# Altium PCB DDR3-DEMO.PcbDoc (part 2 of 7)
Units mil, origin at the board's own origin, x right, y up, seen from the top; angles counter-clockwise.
Board outline 2827 x 2165.35 mil, 8 copper layers (TOP, GND02, ART03, ART04, PWR05, ART06, GND07, BOTTOM); 111 components, 133 nets, 5542 pads, 873 vias.
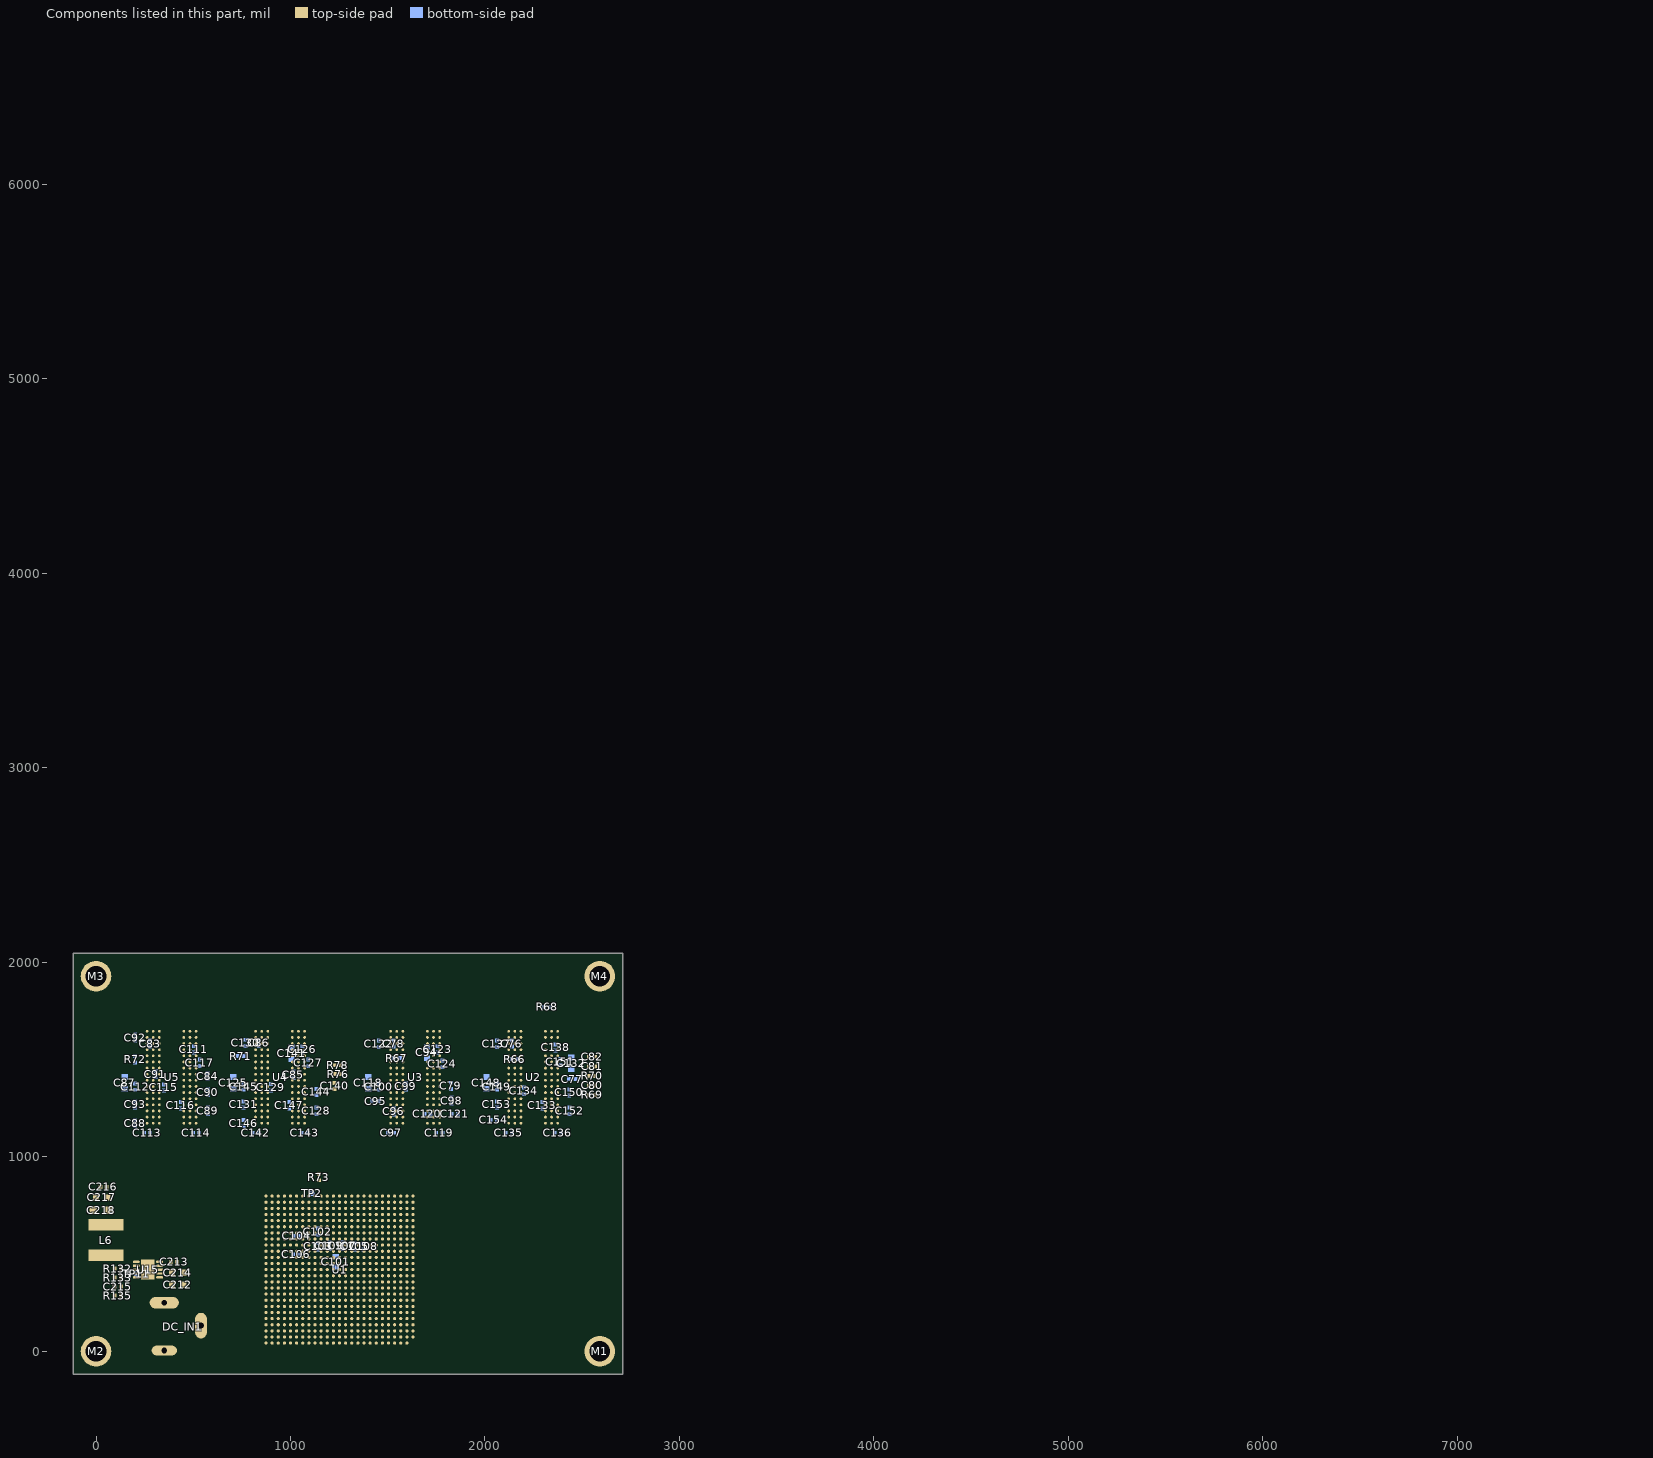
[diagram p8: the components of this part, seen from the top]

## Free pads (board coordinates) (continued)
  round 6 on Drill Drawing: 1(4045.04,1424.5) 1(4045.04,1424.5) 1(4045.04,1459.5) 1(4065.04,1424.5) 1(4072.54,1424.5) 1(4077.04,1436.75) 1(4085.04,1459.5) 1(4085.04,1459.5) 1(4093.04,1436.75) 1(4097.54,1424.5) 1(4105.04,1459.5) 1(4115.04,1424.5) 1(4115.04,1440.25) 1(4115.04,1440.25) 1(4115.04,1440.25) 1(4125.04,1459.5) 1(4129.07,554.03) 1(4129.07,554.03) 1(4129.07,589.03) 1(4135.04,1424.5) 1(4135.04,1424.5) 1(4135.04,1442.58) 1(4135.04,1459.5) 1(4135.04,1459.5) 1(4147.04,1442.58) 1(4149.07,554.03) 1(4155.04,1424.5) 1(4155.04,1459.5) 1(4156.04,2146.59) 1(4156.04,2366.59) 1(4156.04,2586.59) 1(4156.04,2806.59) 1(4156.04,3026.59) 1(4156.04,3246.59) 1(4156.04,3466.59) 1(4156.57,554.03) 1(4161.07,566.28) 1(4165.04,1424.5) 1(4165.04,1441.42) 1(4165.04,1459.5) 1(4165.04,1459.5) 1(4169.07,589.03) 1(4169.07,589.03) 1(4177.07,566.28) 1(4177.54,1441.42) 1(4177.54,1441.42) 1(4177.54,1441.42) 1(4177.54,1459.5) 1(4177.54,1459.5) 1(4181.04,1443.17) 1(4181.04,1443.17) 1(4181.54,1457.75) 1(4181.54,1457.75) 1(4181.57,554.03) 1(4184.04,1446.08) 1(4184.04,1446.08) 1(4184.04,1455.42) 1(4184.04,1455.42) 1(4185.04,1424.5) 1(4185.04,1450.75) 1(4185.04,1450.75) 1(4189.07,589.03) 1(4199.07,554.03) 1(4199.07,569.78) 1(4199.07,569.78) 1(4199.07,569.78) 1(4209.07,589.03) 1(4219.07,554.03) 1(4219.07,554.03) 1(4219.07,572.11) 1(4219.07,589.03) 1(4219.07,589.03) 1(4231.07,572.11) 1(4236.04,2126.59) 1(4236.04,2126.59) 1(4236.04,2166.59) 1(4236.04,2166.59) 1(4236.04,2346.59) 1(4236.04,2346.59) 1(4236.04,2386.59) 1(4236.04,2386.59) 1(4236.04,2566.59) 1(4236.04,2566.59) 1(4236.04,2606.59) 1(4236.04,2606.59) 1(4236.04,2786.59) 1(4236.04,2786.59) 1(4236.04,2826.59) 1(4236.04,2826.59) 1(4236.04,3006.59) 1(4236.04,3006.59) 1(4236.04,3046.59) 1(4236.04,3046.59) 1(4236.04,3226.59) 1(4236.04,3226.59) 1(4236.04,3266.59) 1(4236.04,3266.59) 1(4236.04,3446.59) 1(4236.04,3446.59) 1(4236.04,3486.59) 1(4236.04,3486.59) 1(4239.07,554.03) 1(4239.07,589.03) 1(4249.07,554.03) 1(4249.07,570.95) 1(4249.07,589.03) 1(4249.07,589.03) 1(4261.57,570.95) 1(4261.57,570.95) 1(4261.57,570.95) 1(4261.57,589.03) 1(4261.57,589.03) 1(4265.07,572.7) 1(4265.07,572.7) 1(4265.57,587.28) 1(4265.57,587.28) 1(4268.07,575.61) 1(4268.07,575.61) 1(4268.07,584.95) 1(4268.07,584.95) 1(4269.07,554.03) 1(4269.07,580.28) 1(4269.07,580.28) 1(4291.04,2146.59) 1(4291.04,2146.59) 1(4291.04,2146.59) 1(4291.04,2366.59) 1(4291.04,2366.59) 1(4291.04,2366.59) 1(4291.04,2586.59) 1(4291.04,2586.59) 1(4291.04,2586.59) 1(4291.04,2806.59) 1(4291.04,2806.59) 1(4291.04,2806.59) 1(4291.04,3026.59) 1(4291.04,3026.59) 1(4291.04,3026.59) 1(4291.04,3246.59) 1(4291.04,3246.59) 1(4291.04,3246.59) 1(4291.04,3466.59) 1(4291.04,3466.59) 1(4291.04,3466.59) 1(4386.54,2112.42) 1(4386.54,2162.42) 1(4386.54,2332.11) 1(4386.54,2382.11) 1(4386.54,2551.79) 1(4386.54,2601.79) 1(4386.54,2771.48) 1(4386.54,2821.48) 1(4386.54,2991.16) 1(4386.54,3041.16) 1(4386.54,3210.85) 1(4386.54,3260.85) 1(4386.54,3430.53) 1(4386.54,3480.53) 1(4421.54,2097.42) 1(4421.54,2317.11) 1(4421.54,2536.79) 1(4421.54,2756.48) 1(4421.54,2976.16) 1(4421.54,3195.85) 1(4421.54,3415.53) 1(4426.54,2202.42) 1(4426.54,2422.11) 1(4426.54,2641.79) 1(4426.54,2861.48) 1(4426.54,3081.16) 1(4426.54,3300.85) 1(4426.54,3520.53) 1(4471.54,2097.42) 1(4471.54,2317.11) 1(4471.54,2536.79) 1(4471.54,2756.48) 1(4471.54,2976.16) 1(4471.54,3195.85) 1(4471.54,3415.53) 1(4476.54,2202.42) 1(4476.54,2422.11) 1(4476.54,2641.79) 1(4476.54,2861.48) 1(4476.54,3081.16) 1(4476.54,3300.85) 1(4476.54,3520.53) 1(4519.59,1458.47) 1(4521.54,2097.42) 1(4521.54,2317.11) 1(4521.54,2536.79) 1(4521.54,2756.48) 1(4521.54,2976.16) 1(4521.54,3195.85) 1(4521.54,3415.53) 1(4526.54,2202.42) 1(4526.54,2422.11) 1(4526.54,2641.79) 1(4526.54,2861.48) 1(4526.54,3081.16) 1(4526.54,3300.85) 1(4526.54,3520.53) 1(4526.59,1423.47) 1(4526.59,1423.47) 1(4534.59,1458.47) 1(4534.59,1458.47) 1(4542.59,1423.47) 1(4542.59,1423.47) 1(4549.59,1458.47) 1(4553.6,597.7) 1(4558.59,1423.47) 1(4558.59,1458.47) 1(4560.6,562.7) 1(4560.6,562.7) 1(4564.59,1423.47) 1(4564.59,1458.47) 1(4568.6,597.7) 1(4568.6,597.7) 1(4570.59,1423.47) 1(4570.59,1458.47) 1(4576.54,2202.42) 1(4576.54,2422.11) 1(4576.54,2641.79) 1(4576.54,2861.48) 1(4576.54,3081.16) 1(4576.54,3300.85) 1(4576.54,3520.53) 1(4576.6,562.7) 1(4576.6,562.7) 1(4583.59,1423.47) 1(4583.59,1423.47) 1(4583.59,1458.47) 1(4583.59,1458.47) 1(4583.6,597.7) 1(4592.6,562.7) 1(4592.6,597.7) 1(4593.59,1423.47) 1(4593.59,1423.47) 1(4593.59,1458.47) 1(4593.59,1458.47) 1(4597.59,1425.22) 1(4597.59,1425.22) 1(4597.59,1456.72) 1(4597.59,1456.72) 1(4598.6,562.7) 1(4598.6,597.7) 1(4600.59,1427.55) 1(4600.59,1427.55) 1(4600.59,1454.39) 1(4600.59,1454.39) 1(4603.09,1431.05) 1(4603.09,1431.05) 1(4603.09,1450.89) 1(4603.09,1450.89) 1(4604.6,562.7) 1(4604.6,597.7) 1(4605.09,1435.14) 1(4605.09,1435.14) 1(4605.09,1446.8) 1(4605.09,1446.8) 1(4605.59,1440.97) 1(4605.59,1440.97) 1(4613.09,1458.47) 1(4617.6,562.7) 1(4617.6,562.7) 1(4617.6,597.7) 1(4617.6,597.7) 1(4624.59,1423.47) 1(4624.59,1458.47) 1(4626.54,2202.42) 1(4626.54,2422.11) 1(4626.54,2641.79) 1(4626.54,2861.48) 1(4626.54,3081.16) 1(4626.54,3300.85) 1(4626.54,3520.53) 1(4627.6,562.7) 1(4627.6,562.7) 1(4627.6,597.7) 1(4627.6,597.7) 1(4631.6,564.45) 1(4631.6,564.45) 1(4631.6,595.95) 1(4631.6,595.95) 1(4634.6,566.78) 1(4634.6,566.78) 1(4634.6,593.62) 1(4634.6,593.62) 1(4636.09,1458.47) 1(4637.1,570.28) 1(4637.1,570.28) 1(4637.1,590.12) 1(4637.1,590.12) 1(4639.1,574.37) 1(4639.1,574.37) 1(4639.1,586.03) 1(4639.1,586.03) 1(4639.6,580.2) 1(4639.6,580.2) 1(4644.09,1423.47) 1(4644.09,1440.97) 1(4644.09,1458.47) 1(4647.1,597.7) 1(4658.6,562.7) 1(4658.6,597.7) 1(4665.09,1423.47) 1(4665.09,1440.97) 1(4665.09,1458.47) 1(4670.1,597.7) 1(4678.1,562.7) 1(4678.1,580.2) 1(4678.1,597.7) 1(4699.1,562.7) 1(4699.1,580.2) 1(4699.1,597.7) 1(4751.9,1431.64) 1(4751.9,1431.64) 1(4751.9,1454.97) 1(4751.9,1454.97) 1(4754.4,1425.81) 1(4754.4,1425.81) 1(4754.4,1460.81) 1(4754.4,1460.81) 1(4758.6,562.7) 1(4758.6,562.7) 1(4758.6,586.03) 1(4758.6,586.03) 1(4759.4,1419.97) 1(4759.4,1466.64) 1(4761.1,556.87) 1(4761.1,556.87) 1(4761.1,591.87) 1(4761.1,591.87) 1(4766.1,551.03) 1(4766.1,597.7) 1(4776.9,1431.64) 1(4776.9,1448.56) 1(4776.9,1454.97) 1(4778.4,1451.47) 1(4778.4,1451.47) 1(4780.9,1453.81) 1(4780.9,1453.81) 1(4783.6,562.7) 1(4783.6,579.62) 1(4783.6,586.03) 1(4784.4,1454.97) 1(4784.4,1454.97) 1(4785.1,582.53) 1(4785.1,582.53) 1(4787.6,584.87) 1(4787.6,584.87) 1(4787.9,1453.81) 1(4787.9,1453.81) 1(4790.4,1451.47) 1(4790.4,1451.47) 1(4791.1,586.03) 1(4791.1,586.03) 1(4791.9,1431.64) 1(4791.9,1448.56) 1(4791.9,1448.56) 1(4791.9,1448.56) 1(4793.4,1451.47) 1(4793.4,1451.47) 1(4794.6,584.87) 1(4794.6,584.87) 1(4795.9,1453.81) 1(4795.9,1453.81) 1(4797.1,582.53) 1(4797.1,582.53) 1(4798.6,562.7) 1(4798.6,579.62) 1(4798.6,579.62) 1(4798.6,579.62) 1(4799.4,1454.97) 1(4799.4,1454.97) 1(4800.1,582.53) 1(4800.1,582.53) 1(4802.6,584.87) 1(4802.6,584.87) 1(4802.9,1453.81) 1(4802.9,1453.81) 1(4805.4,1451.47) 1(4805.4,1451.47) 1(4806.1,586.03) 1(4806.1,586.03) 1(4806.9,1431.64) 1(4806.9,1447.97) 1(4806.9,1447.97) 1(4809.6,584.87) 1(4809.6,584.87) 1(4812.1,582.53) 1(4812.1,582.53) 1(4813.6,562.7) 1(4813.6,579.03) 1(4813.6,579.03) 1(4820.9,1464.89) 1(4820.9,1464.89) 1(4820.9,1466.06) 1(4820.9,1466.06) 1(4821.9,1431.64) 1(4821.9,1454.97) 1(4821.9,1464.31) 1(4821.9,1464.31) 1(4821.9,1466.64) 1(4821.9,1466.64) 1(4822.9,1464.89) 1(4822.9,1464.89) 1(4822.9,1466.06) 1(4822.9,1466.06) 1(4827.6,595.95) 1(4827.6,595.95) 1(4827.6,597.12) 1(4827.6,597.12) 1(4828.6,562.7) 1(4828.6,586.03) 1(4828.6,595.37) 1(4828.6,595.37) 1(4828.6,597.7) 1(4828.6,597.7) 1(4829.6,595.95) 1(4829.6,595.95) 1(4829.6,597.12) 1(4829.6,597.12) 1(4851.9,1431.64) 1(4851.9,1466.64) 1(4858.6,562.7) 1(4858.6,597.7) 1(4884.4,1419.97) 1(4884.4,1466.64) 1(4889.4,1425.81) 1(4889.4,1425.81) 1(4889.4,1460.81) 1(4889.4,1460.81) 1(4891.1,551.03) 1(4891.1,597.7) 1(4891.9,1431.64) 1(4891.9,1431.64) 1(4891.9,1454.97) 1(4891.9,1454.97) 1(4896.1,556.87) 1(4896.1,556.87) 1(4896.1,591.87) 1(4896.1,591.87) 1(4898.6,562.7) 1(4898.6,562.7) 1(4898.6,586.03) 1(4898.6,586.03) 1(4924.73,3869.47) 1(4924.73,3869.47) 1(4924.73,3932.47) 1(4928.9,3852.47) 1(4956.07,3869.47) 1(4983.82,3869.47) 1(4990.87,3891.52) 1(5003.4,3932.47) 1(5003.4,3932.47) 1(5015.93,3891.52) 1(5022.98,3869.47) 1(5048.63,1878.63) 1(5048.63,1878.63) 1(5048.63,1912.23) 1(5048.63,1941.63) 1(5048.63,1941.63) 1(5050.73,3932.47) 1(5066.4,3869.47) 1(5066.4,3897.82) 1(5066.4,3897.82) 1(5066.4,3897.82) 1(5069.78,1941.63) 1(5069.78,1941.63) 1(5072.92,1912.23) 1(5072.92,1912.23) 1(5072.92,1912.23) 1(5074.48,1878.63) 1(5074.48,1878.63) 1(5075.27,1938.48) 1(5075.27,1938.48) 1(5076.05,1915.38) 1(5076.05,1915.38) 1(5078.4,1910.13) 1(5078.4,1910.13) 1(5078.4,1920.63) 1(5078.4,1920.63) 1(5078.4,1934.28) 1(5078.4,1934.28) 1(5079.97,1882.83) 1(5079.97,1882.83) 1(5079.97,1927.98) 1(5079.97,1927.98) 1(5082.07,3932.47) 1(5083.1,1889.13) 1(5083.1,1889.13) 1(5083.1,1903.83) 1(5083.1,1903.83) 1(5084.67,1896.48) 1(5084.67,1896.48) 1(5097.33,1428.85) 1(5097.33,1463.85) 1(5103.33,1428.85) 1(5103.33,1463.85) 1(5108.5,1905.93) 1(5108.5,1905.93) 1(5108.5,1914.33) 1(5108.5,1914.33) 1(5109.33,1428.85) 1(5109.33,1463.85) 1(5110.07,1897.53) 1(5110.07,1897.53) 1(5110.07,1922.73) 1(5110.07,1922.73) 1(5113.2,1890.18) 1(5113.2,1890.18) 1(5113.2,1930.08) 1(5113.2,1930.08) 1(5113.73,3869.47) 1(5113.73,3869.47) 1(5113.73,3902.02) 1(5113.73,3932.47) 1(5113.73,3932.47) 1(5117.9,1883.88) 1(5117.9,1883.88) 1(5117.9,1936.38) 1(5117.9,1936.38) 1(5120.09,3755.47) 1(5120.33,1428.85) 1(5120.33,1463.85) 1(5120.33,1463.85) 1(5123.38,1879.68) 1(5123.38,1879.68) 1(5123.38,1940.58) 1(5123.38,1940.58) 1(5129.65,1878.63) 1(5129.65,1878.63) 1(5129.65,1941.63) 1(5129.65,1941.63) 1(5132.53,3902.02) 1(5133.33,1434.68) 1(5133.33,1434.68) 1(5135.92,1879.68) 1(5135.92,1879.68) 1(5135.92,1940.58) 1(5135.92,1940.58) 1(5138.11,3692.47) 1(5138.11,3755.47) 1(5141.4,1883.88) 1(5141.4,1883.88) 1(5141.4,1936.38) 1(5141.4,1936.38) 1(5145.07,3869.47) 1(5145.07,3932.47) 1(5146.1,1890.18) 1(5146.1,1890.18) 1(5146.1,1930.08) 1(5146.1,1930.08) 1(5146.33,1428.85) 1(5146.33,1463.85) 1(5146.33,1463.85) 1(5146.85,553.64) 1(5146.85,588.64) 1(5149.23,1897.53) 1(5149.23,1897.53) 1(5149.23,1922.73) 1(5149.23,1922.73) 1(5150.8,1905.93) 1(5150.8,1905.93) 1(5150.8,1914.33) 1(5150.8,1914.33) 1(5152.85,553.64) 1(5152.85,588.64) 1(5153.33,1428.85) 1(5153.33,1443.43) 1(5153.33,1463.85) 1(5153.33,1463.85) 1(5156.13,3755.47) 1(5158.85,553.64) 1(5158.85,588.64) 1(5165.33,1443.43) 1(5165.33,1443.43) 1(5165.33,1463.85) 1(5165.33,1463.85) 1(5169.33,1462.1) 1(5169.33,1462.1) 1(5169.83,1445.18) 1(5169.83,1445.18) 1(5169.85,553.64) 1(5169.85,588.64) 1(5169.85,588.64) 1(5172.33,1448.68) 1(5172.33,1448.68) 1(5172.33,1458.02) 1(5172.33,1458.02) 1(5173.33,1453.35) 1(5173.33,1453.35) 1(5174.63,1941.63) 1(5176.73,3869.47) 1(5176.73,3899.92) 1(5176.73,3932.47) 1(5176.73,3932.47) 1(5179.96,3719.77) 1(5179.96,3719.77) 1(5179.96,3728.17) 1(5179.96,3728.17) 1(5181.53,3711.37) 1(5181.53,3711.37) 1(5181.53,3736.57) 1(5181.53,3736.57) 1(5182.85,559.47) 1(5182.85,559.47) 1(5183.33,1428.85) 1(5183.33,1428.85) 1(5183.33,1446.93) 1(5183.33,1463.85) 1(5183.33,1463.85) 1(5184.66,3704.02) 1(5184.66,3704.02) 1(5184.66,3743.92) 1(5184.66,3743.92) 1(5189.36,3697.72) 1(5189.36,3697.72) 1(5189.36,3750.22) 1(5189.36,3750.22) 1(5192.65,1878.63) 1(5192.65,1941.63) 1(5194.84,3693.52) 1(5194.84,3693.52) 1(5194.84,3754.42) 1(5194.84,3754.42) 1(5195.33,1446.93) 1(5195.85,553.64) 1(5195.85,588.64) 1(5195.85,588.64) 1(5196.32,3899.92) 1(5196.32,3899.92) 1(5196.32,3899.92) 1(5196.32,3932.47) 1(5196.32,3932.47) 1(5201.11,3692.47) 1(5201.11,3692.47) 1(5201.11,3755.47) 1(5201.11,3755.47) 1(5201.8,3903.07) 1(5201.8,3903.07) 1(5202.58,3929.32) 1(5202.58,3929.32) 1(5202.85,553.64) 1(5202.85,568.22) 1(5202.85,588.64) 1(5202.85,588.64) 1(5203.33,1428.85) 1(5203.33,1463.85) 1(5206.5,3908.32) 1(5206.5,3908.32) 1(5206.5,3925.12) 1(5206.5,3925.12) 1(5207.38,3693.52) 1(5207.38,3693.52) 1(5207.38,3754.42) 1(5207.38,3754.42) 1(5208.07,3869.47) 1(5208.07,3916.72) 1(5208.07,3916.72) 1(5210.67,1941.63) 1(5212.33,1428.85) 1(5212.33,1428.85) 1(5212.33,1463.85) 1(5212.33,1463.85) 1(5212.86,3697.72) 1(5212.86,3697.72) 1(5212.86,3750.22) 1(5212.86,3750.22) 1(5214.85,568.22) 1(5214.85,568.22) 1(5214.85,588.64) 1(5214.85,588.64) 1(5217.56,3704.02) 1(5217.56,3704.02) 1(5217.56,3743.92) 1(5217.56,3743.92) 1(5218.85,586.89) 1(5218.85,586.89) 1(5219.35,569.97) 1(5219.35,569.97) 1(5220.69,3711.37) 1(5220.69,3711.37) 1(5220.69,3736.57) 1(5220.69,3736.57) 1(5221.85,573.47) 1(5221.85,573.47) 1(5221.85,582.81) 1(5221.85,582.81) 1(5222.26,3719.77) 1(5222.26,3719.77) 1(5222.26,3728.17) 1(5222.26,3728.17) 1(5222.33,1428.85) 1(5222.33,1428.85) 1(5222.33,1463.85) 1(5222.33,1463.85) 1(5222.85,578.14) 1(5222.85,578.14) 1(5226.33,1430.6) 1(5226.33,1430.6) 1(5226.33,1462.1) 1(5226.33,1462.1) 1(5229.33,1432.93) 1(5229.33,1432.93) 1(5229.33,1459.77) 1(5229.33,1459.77) 1(5231.83,1436.43) 1(5231.83,1436.43) 1(5231.83,1456.27) 1(5231.83,1456.27) 1(5232.85,553.64) 1(5232.85,553.64) 1(5232.85,571.72) 1(5232.85,588.64) 1(5232.85,588.64) 1(5233.83,1440.52) 1(5233.83,1440.52) 1(5233.83,1452.18) 1(5233.83,1452.18) 1(5234.33,1446.35) 1(5234.33,1446.35) 1(5237.63,1941.63) 1(5240.83,1428.85) 1(5244.85,571.72) 1(5245.33,1441.1) 1(5248.44,3692.47) 1(5248.44,3718.72) 1(5248.44,3755.47) 1(5248.44,3755.47) 1(5252.85,553.64) 1(5252.85,588.64) 1(5253.33,1463.85) 1(5253.33,1463.85) 1(5255.65,1878.63) 1(5255.65,1941.63) 1(5261.33,1441.1) 1(5261.85,553.64) 1(5261.85,553.64) 1(5261.85,588.64) 1(5261.85,588.64) 1(5265.83,1428.85) 1(5267.24,3718.72) 1(5267.24,3718.72) 1(5267.24,3755.47) 1(5267.24,3755.47) 1(5271.83,1428.85) 1(5271.83,1463.85) 1(5271.83,1463.85) 1(5271.85,553.64) 1(5271.85,553.64) 1(5271.85,588.64) 1(5271.85,588.64) 1(5273.51,3752.32) 1(5273.51,3752.32) 1(5273.67,1941.63) 1(5274.29,3721.87) 1(5274.29,3721.87) 1(5275.85,555.39) 1(5275.85,555.39) 1(5275.85,586.89) 1(5275.85,586.89) 1(5278.21,3728.17) 1(5278.21,3728.17) 1(5278.21,3744.97) 1(5278.21,3744.97) 1(5278.85,557.72) 1(5278.85,557.72) 1(5278.85,584.56) 1(5278.85,584.56) 1(5279.78,3736.57) 1(5279.78,3736.57) 1(5281.35,561.22) 1(5281.35,561.22) 1(5281.35,581.06) 1(5281.35,581.06) 1(5283.35,565.31) 1(5283.35,565.31) 1(5283.35,576.97) 1(5283.35,576.97) 1(5283.85,571.14) 1(5283.85,571.14) 1(5290.35,553.64) 1(5294.83,1428.85) 1(5294.83,1428.85) 1(5294.83,1463.85) 1(5294.85,565.89) 1(5297.5,1905.93) 1(5297.5,1905.93) 1(5297.5,1914.33) 1(5297.5,1914.33) 1(5299.07,1897.53) 1(5299.07,1897.53) 1(5299.07,1922.73) 1(5299.07,1922.73) 1(5300.83,1444.6) 1(5300.83,1444.6) 1(5301.33,1449.85) 1(5301.33,1449.85) 1(5301.83,1439.35) 1(5301.83,1439.35) 1(5301.95,3877.87) 1(5302.2,1890.18) 1(5302.2,1890.18) 1(5302.2,1930.08) 1(5302.2,1930.08) 1(5302.85,588.64) 1(5302.85,588.64) 1(5303.33,1435.85) 1(5303.33,1435.85) 1(5303.33,1455.68) 1(5303.33,1455.68) 1(5305.08,3916.72) 1(5305.08,3916.72) 1(5305.83,1459.18) 1(5305.83,1459.18) 1(5306.33,1432.35) 1(5306.33,1432.35) 1(5306.65,3924.07) 1(5306.65,3924.07) 1(5306.9,1883.88) 1(5306.9,1883.88) 1(5306.9,1936.38) 1(5306.9,1936.38) 1(5307.43,3909.37) 1(5307.43,3909.37) 1(5308.22,3872.62) 1(5308.22,3872.62) 1(5309.33,1462.1) 1(5309.33,1462.1) 1(5309.83,1430.02) 1(5309.83,1430.02) 1(5310.57,3929.32) 1(5310.57,3929.32) 1(5310.85,565.89) 1(5312.38,1879.68) 1(5312.38,1879.68) 1(5312.38,1940.58) 1(5312.38,1940.58) 1(5312.92,3905.17) 1(5312.92,3905.17) 1(5313.33,1428.85) 1(5313.33,1428.85) 1(5313.83,1463.85) 1(5313.83,1463.85) 1(5315.27,3869.47) 1(5315.27,3869.47) 1(5315.35,553.64) 1(5316.05,3932.47) 1(5316.05,3932.47) 1(5316.83,1428.85) 1(5316.83,1428.85) 1(5317.83,1463.85) 1(5317.83,1463.85) 1(5318.65,1878.63) 1(5318.65,1878.63) 1(5318.65,1941.63) 1(5318.65,1941.63) 1(5320.33,1430.02) 1(5320.33,1430.02) 1(5321.33,1462.68) 1(5321.33,1462.68) 1(5321.35,553.64) 1(5321.35,588.64) 1(5321.35,588.64) 1(5321.53,3869.47) 1(5321.53,3869.47) 1(5321.53,3932.47) 1(5321.53,3932.47) 1(5322.32,3903.07) 1(5322.32,3903.07) 1(5323.33,1431.77) 1(5323.33,1431.77) 1(5324.33,1460.93) 1(5324.92,1879.68) 1(5324.92,1879.68) 1(5324.92,1940.58) 1(5324.92,1940.58) 1(5325.83,1434.1) 1(5327.02,3930.37) 1(5327.02,3930.37) 1(5327.8,3872.62) 1(5327.8,3872.62) 1(5329.37,3898.87) 1(5329.37,3898.87) 1(5330.4,1883.88) 1(5330.4,1883.88) 1(5330.4,1936.38) 1(5330.4,1936.38) 1(5331.72,3925.12) 1(5332.5,3877.87) 1(5332.5,3877.87) 1(5333.28,3892.57) 1(5333.28,3892.57) 1(5333.33,1428.85) 1(5333.33,1428.85) 1(5333.33,1446.93) 1(5333.33,1463.85) 1(5333.33,1463.85) 1(5334.85,3885.22) 1(5334.85,3885.22) 1(5335.1,1890.18) 1(5335.1,1890.18) 1(5335.1,1930.08) 1(5335.1,1930.08) 1(5338.23,1897.53) 1(5338.23,1897.53) 1(5338.23,1922.73) 1(5338.23,1922.73) 1(5339.8,1905.93) 1(5339.8,1905.93) 1(5339.8,1914.33) 1(5339.8,1914.33) 1(5344.35,553.64) 1(5344.35,553.64) 1(5344.35,588.64) 1(5345.33,1446.93) 1(5350.35,569.39) 1(5350.35,569.39) 1(5350.85,574.64) 1(5350.85,574.64) 1(5351.35,564.14) 1(5351.35,564.14) 1(5352.85,560.64) 1(5352.85,560.64) 1(5352.85,580.47) 1(5352.85,580.47) 1(5353.33,1428.85) 1(5353.33,1463.85) 1(5355.35,583.97) 1(5355.35,583.97) 1(5355.85,557.14) 1(5355.85,557.14) 1(5358.85,586.89) 1(5358.85,586.89) 1(5359.35,554.81) 1(5359.35,554.81) 1(5361.28,1878.63) 1(5361.28,1941.63) 1(5361.28,1941.63) 1(5362.85,553.64) 1(5362.85,553.64) 1(5363.35,588.64) 1(5363.35,588.64) 1(5363.38,3932.47) 1(5366.35,553.64) 1(5366.35,553.64) 1(5367.35,588.64) 1(5367.35,588.64) 1(5369.85,554.81) 1(5369.85,554.81) 1(5370.85,587.47) 1(5370.85,587.47) 1(5372.85,556.56) 1(5372.85,556.56) 1(5373.66,3700.87) 1(5373.85,585.72) 1(5375.35,558.89) 1(5376.79,3739.72) 1(5376.79,3739.72) 1(5378.36,3747.07) 1(5378.36,3747.07) 1(5379.14,3732.37) 1(5379.14,3732.37) 1(5379.93,3695.62) 1(5379.93,3695.62) 1(5381.4,3869.47) 1(5381.4,3932.47) 1(5381.65,1889.13) 1(5381.65,1889.13) 1(5382.28,3752.32) 1(5382.28,3752.32) 1(5382.85,553.64) 1(5382.85,553.64) 1(5382.85,571.72) 1(5382.85,588.64) 1(5382.85,588.64) 1(5384.63,3728.17) 1(5384.63,3728.17) 1(5386.98,3692.47) 1(5386.98,3692.47) 1(5387.76,3755.47) 1(5387.76,3755.47) 1(5393.24,3692.47) 1(5393.24,3692.47) 1(5393.24,3755.47) 1(5393.24,3755.47) 1(5394.03,3726.07) 1(5394.03,3726.07) 1(5394.85,571.72) 1(5398.73,3753.37) 1(5398.73,3753.37) 1(5399.42,3932.47) 1(5399.51,3695.62) 1(5399.51,3695.62) 1(5401.08,3721.87) 1(5401.08,3721.87) 1(5402.02,1878.63) 1(5402.02,1941.63) 1(5402.02,1941.63) 1(5402.85,553.64) 1(5402.85,588.64) 1(5403.43,3748.12) 1(5404.21,3700.87) 1(5404.21,3700.87) 1(5404.99,3715.57) 1(5404.99,3715.57) 1(5406.56,3708.22) 1(5406.56,3708.22) 1(5424.82,3869.47) 1(5431.87,3891.52) 1(5443.71,3692.47) 1(5443.71,3755.47) 1(5444.4,3932.47) 1(5444.4,3932.47) 1(5453.11,3692.47) 1(5453.11,3755.47) 1(5456.93,3891.52) 1(5462.51,3692.47) 1(5462.51,3755.47) 1(5463.98,3869.47) 1(5480.64,1432.02) 1(5480.64,1432.02) 1(5480.64,1455.35) 1(5480.64,1455.35) 1(5483.14,1426.19) 1(5483.14,1426.19) 1(5483.14,1461.19) 1(5483.14,1461.19) 1(5487.82,3897.82) 1(5487.82,3897.82) 1(5488.14,1420.35) 1(5488.14,1467.02) 1(5488.6,3907.27) 1(5488.6,3907.27) 1(5489.38,3888.37) 1(5489.38,3888.37) 1(5491.2,1887.03) 1(5491.73,3882.07) 1(5491.73,3882.07) 1(5491.73,3917.77) 1(5491.73,3917.77) 1(5492.85,553.64) 1(5492.85,553.64) 1(5492.85,576.97) 1(5492.85,576.97) 1(5494.33,1925.88) 1(5494.33,1925.88) 1(5495.35,547.81) 1(5495.35,547.81) 1(5495.35,582.81) 1(5495.35,582.81) 1(5495.65,3924.07) 1(5495.65,3924.07) 1(5495.9,1933.23) 1(5495.9,1933.23) 1(5496.43,3875.77) 1(5496.43,3875.77) 1(5496.68,1918.53) 1(5496.68,1918.53) 1(5497.47,1881.78) 1(5497.47,1881.78) 1(5498.88,3692.47) 1(5498.88,3692.47) 1(5498.88,3755.47) 1(5498.88,3755.47) 1(5499.82,1938.48) 1(5499.82,1938.48) 1(5500.35,541.97) 1(5500.35,588.64) 1(5501.13,3929.32) 1(5501.13,3929.32) 1(5501.92,3871.57) 1(5501.92,3871.57) 1(5502.17,1914.33) 1(5502.17,1914.33) 1(5504.52,1878.63) 1(5504.52,1878.63) 1(5505.3,1941.63) 1(5505.3,1941.63) 1(5507.4,3869.47) 1(5507.4,3869.47) 1(5508.18,3932.47) 1(5508.18,3932.47) 1(5510.78,1878.63) 1(5510.78,1878.63) 1(5510.78,1941.63) 1(5510.78,1941.63) 1(5511.57,1912.23) 1(5511.57,1912.23) 1(5511.64,1443.69) 1(5511.64,1443.69) 1(5512.64,1439.02) 1(5512.64,1439.02) 1(5512.64,1448.35) 1(5512.64,1448.35) 1(5512.88,3869.47) 1(5512.88,3869.47) 1(5514.45,3932.47) 1(5514.45,3932.47) 1(5514.54,3692.47) 1(5514.54,3692.47) 1(5514.54,3755.47) 1(5514.54,3755.47) 1(5514.64,1434.94) 1(5514.64,1434.94) 1(5514.64,1452.44) 1(5514.64,1452.44) 1(5516.27,1939.53) 1(5516.27,1939.53) 1(5517.05,1881.78) 1(5517.05,1881.78) 1(5517.64,1432.6) 1(5517.64,1432.6) 1(5517.64,1454.77) 1(5517.64,1454.77) 1(5518.37,3871.57) 1(5518.37,3871.57) 1(5518.62,1908.03) 1(5518.62,1908.03) 1(5519.93,3930.37) 1(5519.93,3930.37) 1(5520.64,1432.02) 1(5520.64,1432.02) 1(5520.64,1455.35) 1(5520.64,1455.35) 1(5520.81,3695.62) 1(5520.81,3695.62) 1(5520.81,3752.32) 1(5520.81,3752.32) 1(5520.97,1934.28) 1(5521.75,1887.03) 1(5521.75,1887.03) 1(5522.53,1901.73) 1(5522.53,1901.73) 1(5523.07,3874.72) 1(5523.07,3874.72) 1(5523.64,1432.6) 1(5523.64,1432.6) 1(5523.64,1454.77) 1(5523.64,1454.77) 1(5523.85,565.31) 1(5523.85,565.31) 1(5524.1,1894.38) 1(5524.1,1894.38) 1(5524.63,3927.22) 1(5524.85,560.64) 1(5524.85,560.64) 1(5524.85,569.97) 1(5524.85,569.97) 1(5525.51,3699.82) 1(5525.51,3699.82) 1(5525.51,3748.12) 1(5525.51,3748.12) 1(5526.64,1434.94) 1(5526.64,1434.94) 1(5526.64,1452.44) 1(5526.64,1452.44) 1(5526.85,556.56) 1(5526.85,556.56) 1(5526.85,574.06) 1(5526.85,574.06) 1(5526.98,3878.92) 1(5528.64,1439.02) 1(5528.64,1439.02) 1(5528.64,1448.35) 1(5528.64,1448.35) 1(5529.14,1443.69) 1(5529.14,1443.69) 1(5529.43,3706.12) 1(5529.43,3706.12) 1(5529.43,3741.82) 1(5529.43,3741.82) 1(5529.85,554.22) 1(5529.85,554.22) 1(5529.85,576.39) 1(5529.85,576.39) 1(5532.56,3713.47) 1(5532.56,3713.47) 1(5532.56,3734.47) 1(5532.56,3734.47) 1(5532.85,553.64) 1(5532.85,553.64) 1(5532.85,576.97) 1(5532.85,576.97) 1(5533.34,3723.97) 1(5533.34,3723.97) 1(5535.85,554.22) 1(5535.85,554.22) 1(5535.85,576.39) 1(5535.85,576.39) 1(5538.85,556.56) 1(5538.85,556.56) 1(5538.85,574.06) 1(5538.85,574.06) 1(5540.85,560.64) 1(5540.85,560.64) 1(5540.85,569.97) 1(5540.85,569.97) 1(5541.35,565.31) 1(5541.35,565.31) 1(5542.14,1432.02) 1(5542.14,1450.1) 1(5542.14,1467.02) 1(5544.64,1453.02) 1(5544.64,1453.02) 1(5547.14,1454.77) 1(5547.14,1454.77) 1(5551.14,1455.35) 1(5551.14,1455.35) 1(5553.17,3869.47) 1(5553.17,3893.62) 1(5553.17,3932.47) 1(5554.14,1454.77) 1(5554.14,1454.77) 1(5554.35,553.64) 1(5554.35,571.72) 1(5554.35,588.64) 1(5556.85,574.64) 1(5556.85,574.64) 1(5557.64,1452.44) 1(5557.64,1452.44) 1(5559.14,1432.02) 1(5559.14,1448.94) 1(5559.14,1448.94) 1(5559.35,576.39) 1(5559.35,576.39) 1(5561.25,1878.63) 1(5561.25,1941.63) 1(5563.35,576.97) 1(5563.35,576.97) 1(5563.44,3692.47) 1(5563.44,3692.47) 1(5563.44,3725.02) 1(5563.44,3755.47) 1(5563.44,3755.47) 1(5565.64,1432.02) 1(5565.64,1448.94) 1(5565.64,1455.35) 1(5566.35,576.39) 1(5566.35,576.39) 1(5566.48,3911.47) 1(5567.14,1451.85) 1(5567.14,1451.85) 1(5569.64,1454.19) 1(5569.64,1454.19) 1(5569.85,574.06) 1(5569.85,574.06) 1(5570.65,1878.63) 1(5570.65,1941.63) 1(5571.35,553.64) 1(5571.35,570.56) 1(5571.35,570.56) 1(5573.14,1455.35) 1(5573.14,1455.35) 1(5576.64,1454.19) 1(5576.64,1454.19) 1(5577.85,553.64) 1(5577.85,570.56) 1(5577.85,576.97) 1(5579.14,1451.85) 1(5579.14,1451.85) 1(5579.35,573.47) 1(5579.35,573.47) 1(5580.05,1878.63) 1(5580.05,1941.63) 1(5580.64,1432.02) 1(5580.64,1448.94) 1(5580.64,1448.94) 1(5580.64,1448.94) 1(5581.85,575.81) 1(5581.85,575.81) 1(5582.14,1451.85) 1(5582.14,1451.85) 1(5582.24,3725.02) 1(5582.93,3932.47) 1(5584.64,1454.19) 1(5584.64,1454.19) 1(5585.35,576.97) 1(5585.35,576.97) 1(5587.63,3869.47) 1(5588.14,1455.35) 1(5588.14,1455.35) 1(5588.85,575.81) 1(5588.85,575.81) 1(5591.35,573.47) 1(5591.35,573.47) 1(5591.64,1454.19) 1(5591.64,1454.19) 1(5592.85,553.64) 1(5592.85,570.56) 1(5592.85,570.56) 1(5592.85,570.56) 1(5594.14,1451.85) 1(5594.14,1451.85) 1(5594.35,573.47) 1(5594.35,573.47) 1(5594.78,3692.47) 1(5594.78,3755.47) 1(5595.64,1432.02) 1(5595.64,1448.35) 1(5595.64,1448.35) 1(5596.85,575.81) 1(5596.85,575.81) 1(5600.35,576.97) 1(5600.35,576.97) 1(5603.85,575.81) 1(5603.85,575.81) 1(5606.35,573.47) 1(5606.35,573.47) 1(5607.85,553.64) 1(5607.85,569.97) 1(5607.85,569.97) 1(5613.14,1420.35) 1(5613.14,1467.02) 1(5616.42,1878.63) 1(5616.42,1878.63) 1(5616.42,1941.63) 1(5616.42,1941.63) 1(5618.14,1426.19) 1(5618.14,1426.19) 1(5618.14,1461.19) 1(5618.14,1461.19) 1(5620.64,1432.02) 1(5620.64,1432.02) 1(5620.64,1455.35) 1(5620.64,1455.35) 1(5624,3869.47) 1(5624,3932.47) 1(5625.35,541.97) 1(5625.35,588.64) 1(5630.35,547.81) 1(5630.35,547.81) 1(5630.35,582.81) 1(5630.35,582.81) 1(5632.08,1878.63) 1(5632.08,1878.63) 1(5632.08,1941.63) 1(5632.08,1941.63) 1(5632.85,553.64) 1(5632.85,553.64) 1(5632.85,576.97) 1(5632.85,576.97) 1(5633.4,3869.47) 1(5633.4,3932.47) 1(5638.35,1881.78) 1(5638.35,1881.78) 1(5638.35,1938.48) 1(5638.35,1938.48) 1(5642.8,3869.47) 1(5642.8,3932.47) 1(5643.05,1885.98) 1(5643.05,1885.98) 1(5643.05,1934.28) 1(5643.05,1934.28) 1(5646.97,1892.28) 1(5646.97,1892.28) 1(5646.97,1927.98) 1(5646.97,1927.98) 1(5650.1,1899.63) 1(5650.1,1899.63) 1(5650.1,1920.63) 1(5650.1,1920.63) 1(5650.88,1910.13) 1(5650.88,1910.13) 1(5678.38,3869.47) 1(5678.38,3932.47) 1(5678.38,3932.47) 1(5680.98,1878.63) 1(5680.98,1878.63) 1(5680.98,1911.18) 1(5680.98,1941.63) 1(5680.98,1941.63) 1(5699.78,1911.18) 1(5712.32,1878.63) 1(5712.32,1941.63) 1(5714.42,3869.47) 1(5714.42,3869.47) 1(5714.42,3932.47) 1(5739.03,3897.82) 1(5739.03,3897.82) 1(5739.03,3905.17) 1(5739.03,3905.17) 1(5740.6,3889.42) 1(5740.6,3889.42) 1(5740.6,3911.47) 1(5740.6,3911.47) 1(5743.73,3882.07) 1(5743.73,3882.07) 1(5743.73,3918.82) 1(5743.73,3918.82) 1(5748.43,3875.77) 1(5748.43,3875.77) 1(5748.43,3925.12) 1(5748.43,3925.12) 1(5753.13,3929.32) 1(5753.13,3929.32) 1(5753.92,3871.57) 1(5753.92,3871.57) 1(5759.4,3932.47) 1(5759.4,3932.47) 1(5761.75,3869.47) 1(5761.75,3869.47) 1(5764.1,3900.97) 1(5764.88,3932.47) 1(5764.88,3932.47) 1(5769.58,3871.57) 1(5769.58,3871.57) 1(5771.15,3930.37) 1(5771.15,3930.37) 1(5775.07,3875.77) 1(5775.07,3875.77) 1(5775.85,3926.17) 1(5779.77,3882.07) 1(5779.77,3882.07) 1(5779.77,3900.97) 1(5779.77,3900.97) 1(5779.9,3852.47) 1(5886.76,1422.69) 1(5886.76,1437.27) 1(5886.76,1457.69) 1(5886.76,1457.69) 1(5898.76,1437.27) 1(5898.76,1437.27) 1(5898.76,1457.69) 1(5898.76,1457.69) 1(5902.76,1455.94) 1(5902.76,1455.94) 1(5903.26,1439.02) 1(5903.26,1439.02) 1(5905.76,1442.52) 1(5905.76,1442.52) 1(5905.76,1451.86) 1(5905.76,1451.86) 1(5906.76,1447.19) 1(5906.76,1447.19) 1(5910.96,554.03) 1(5910.96,568.61) 1(5910.96,589.03) 1(5910.96,589.03) 1(5916.76,1422.69) 1(5916.76,1439.61) 1(5916.76,1457.69) 1(5916.76,1457.69) 1(5922.96,568.61) 1(5922.96,568.61) 1(5922.96,589.03) 1(5922.96,589.03) 1(5926.96,587.28) 1(5926.96,587.28) 1(5927.46,570.36) 1(5927.46,570.36) 1(5929.26,1439.61) 1(5929.26,1439.61) 1(5929.26,1439.61) 1(5929.26,1457.69) 1(5929.26,1457.69) 1(5929.96,573.86) 1(5929.96,573.86) 1(5929.96,583.2) 1(5929.96,583.2) 1(5930.96,578.53) 1(5930.96,578.53) 1(5932.76,1441.36) 1(5932.76,1441.36) 1(5933.26,1455.94) 1(5933.26,1455.94) 1(5935.76,1444.27) 1(5935.76,1444.27) 1(5935.76,1453.61) 1(5935.76,1453.61) 1(5936.76,1422.69) 1(5936.76,1448.94) 1(5936.76,1448.94) 1(5940.96,554.03) 1(5940.96,570.95) 1(5940.96,589.03) 1(5940.96,589.03) 1(5946.76,1422.69) 1(5946.76,1422.69) 1(5946.76,1440.77) 1(5946.76,1457.69) 1(5946.76,1457.69) 1(5953.46,570.95) 1(5953.46,570.95) 1(5953.46,570.95) 1(5953.46,589.03) 1(5953.46,589.03) 1(5956.96,572.7) 1(5956.96,572.7) 1(5957.46,587.28) 1(5957.46,587.28) 1(5958.76,1440.77) 1(5959.96,575.61) 1(5959.96,575.61) 1(5959.96,584.95) 1(5959.96,584.95) 1(5960.96,554.03) 1(5960.96,580.28) 1(5960.96,580.28) 1(5966.76,1422.69) 1(5966.76,1457.69) 1(5970.96,554.03) 1(5970.96,554.03) 1(5970.96,572.11) 1(5970.96,589.03) 1(5970.96,589.03) 1(5974.26,1438.44) 1(5974.26,1438.44) 1(5974.76,1443.69) 1(5974.76,1443.69) 1(5975.26,1433.19) 1(5975.26,1433.19) 1(5976.76,1429.69) 1(5976.76,1429.69) 1(5976.76,1449.52) 1(5976.76,1449.52) 1(5979.26,1453.02) 1(5979.26,1453.02) 1(5979.76,1426.19) 1(5979.76,1426.19) 1(5982.76,1455.94) 1(5982.76,1455.94) 1(5982.96,572.11) 1(5983.26,1423.86) 1(5983.26,1423.86) 1(5986.76,1422.69) 1(5986.76,1422.69) 1(5987.26,1457.69) 1(5987.26,1457.69) 1(5990.26,1422.69) 1(5990.26,1422.69) 1(5990.96,554.03) 1(5990.96,589.03) 1(5991.26,1457.69) 1(5991.26,1457.69) 1(5993.76,1423.86) 1(5993.76,1423.86) 1(5994.76,1456.52) 1(5994.76,1456.52) 1(5996.76,1425.61) 1(5996.76,1425.61) 1(5997.76,1454.77) 1(5998.46,569.78) 1(5998.46,569.78) 1(5998.96,575.03) 1(5998.96,575.03) 1(5999.26,1427.94) 1(5999.46,564.53) 1(5999.46,564.53) 1(6000.96,561.03) 1(6000.96,561.03) 1(6000.96,580.86) 1(6000.96,580.86) 1(6003.46,584.36) 1(6003.46,584.36) 1(6003.96,557.53) 1(6003.96,557.53) 1(6006.96,587.28) 1(6006.96,587.28) 1(6007.46,555.2) 1(6007.46,555.2) 1(6010.76,1422.69) 1(6010.76,1457.69) 1(6010.96,554.03) 1(6010.96,554.03) 1(6011.46,589.03) 1(6011.46,589.03) 1(6014.46,554.03) 1(6014.46,554.03) 1(6015.46,589.03) 1(6015.46,589.03) 1(6016.76,1422.69) 1(6016.76,1457.69) 1(6017.96,555.2) 1(6017.96,555.2) 1(6018.96,587.86) 1(6018.96,587.86) 1(6020.96,556.95) 1(6020.96,556.95) 1(6021.96,586.11) 1(6022.76,1422.69) 1(6022.76,1457.69) 1(6023.46,559.28) 1(6034.96,554.03) 1(6034.96,589.03) 1(6036.26,1427.36) 1(6038.26,1448.94) 1(6038.26,1448.94) 1(6039.26,1453.02) 1(6039.26,1453.02) 1(6039.76,1444.86) 1(6039.76,1444.86) 1(6040.26,1424.44) 1(6040.26,1424.44) 1(6040.96,554.03) 1(6040.96,589.03) 1(6041.76,1455.94) 1(6041.76,1455.94) 1(6043.26,1442.52) 1(6043.26,1442.52) 1(6044.76,1422.69) 1(6044.76,1422.69) 1(6045.26,1457.69) 1(6045.26,1457.69) 1(6046.96,554.03) 1(6046.96,589.03) 1(6048.76,1422.69) 1(6048.76,1422.69) 1(6048.76,1457.69) 1(6048.76,1457.69) 1(6049.26,1441.36) 1(6049.26,1441.36) 1(6052.26,1456.52) 1(6052.26,1456.52) 1(6052.76,1424.44) 1(6052.76,1424.44) 1(6053.76,1439.02) 1(6053.76,1439.02) 1(6055.26,1453.61) 1(6055.76,1427.36) 1(6055.76,1427.36) 1(6056.26,1435.52) 1(6056.26,1435.52) 1(6057.26,1431.44) 1(6057.26,1431.44) 1(6060.46,558.7) 1(6062.46,580.28) 1(6062.46,580.28) 1(6063.46,584.36) 1(6063.46,584.36) 1(6063.96,576.2) 1(6063.96,576.2) 1(6064.46,555.78) 1(6064.46,555.78) 1(6065.96,587.28) 1(6065.96,587.28) 1(6067.46,573.86) 1(6067.46,573.86) 1(6068.96,554.03) 1(6068.96,554.03) 1(6069.46,589.03) 1(6069.46,589.03) 1(6070.76,1422.69) 1(6070.76,1457.69) 1(6072.96,554.03) 1(6072.96,554.03) 1(6072.96,589.03) 1(6072.96,589.03) 1(6073.46,572.7) 1(6073.46,572.7) 1(6076.46,587.86) 1(6076.46,587.86) 1(6076.76,1422.69) 1(6076.76,1457.69) 1(6076.96,555.78) 1(6076.96,555.78) 1(6077.96,570.36) 1(6077.96,570.36) 1(6079.46,584.95) 1(6079.96,558.7) 1(6079.96,558.7) 1(6080.46,566.86) 1(6080.46,566.86) 1(6081.46,562.78) 1(6081.46,562.78) 1(6082.76,1422.69) 1(6082.76,1457.69) 1(6093.26,1437.86) 1(6093.26,1437.86) 1(6093.26,1442.52) 1(6093.26,1442.52) 1(6094.26,1433.19) 1(6094.26,1433.19) 1(6094.26,1447.19) 1(6094.26,1447.19) 1(6094.96,554.03) 1(6094.96,589.03) 1(6096.26,1429.11) 1(6096.26,1429.11) 1(6096.26,1451.27) 1(6096.26,1451.27) 1(6099.26,1425.61) 1(6099.26,1425.61) 1(6099.26,1454.77) 1(6099.26,1454.77) 1(6100.96,554.03) 1(6100.96,589.03) 1(6102.76,1423.27) 1(6102.76,1423.27) 1(6102.76,1457.11) 1(6102.76,1457.11) 1(6106.76,1422.69) 1(6106.76,1422.69) 1(6106.76,1457.69) 1(6106.76,1457.69) 1(6106.96,554.03) 1(6106.96,589.03) 1(6110.76,1423.27) 1(6110.76,1423.27) 1(6110.76,1457.11) 1(6110.76,1457.11) 1(6114.26,1425.61) 1(6114.26,1425.61) 1(6114.26,1454.77) 1(6114.26,1454.77) 1(6117.26,1429.11) 1(6117.26,1429.11) 1(6117.26,1451.27) 1(6117.26,1451.27) 1(6117.46,569.2) 1(6117.46,569.2) 1(6117.46,573.86) 1(6117.46,573.86) 1(6118.46,564.53) 1(6118.46,564.53) 1(6118.46,578.53) 1(6118.46,578.53) 1(6119.26,1433.19) 1(6119.26,1433.19) 1(6119.26,1447.19) 1(6119.26,1447.19) 1(6120.26,1437.86) 1(6120.26,1437.86) 1(6120.26,1442.52) 1(6120.26,1442.52) 1(6120.46,560.45) 1(6120.46,560.45) 1(6120.46,582.61) 1(6120.46,582.61) 1(6123.46,556.95) 1(6123.46,556.95) 1(6123.46,586.11) 1(6123.46,586.11) 1(6125.26,1422.69) 1(6125.26,1457.69) 1(6125.26,1457.69) 1(6126.96,554.61) 1(6126.96,554.61) 1(6126.96,588.45) 1(6126.96,588.45) 1(6130.96,554.03) 1(6130.96,554.03) 1(6130.96,589.03) 1(6130.96,589.03) 1(6134.96,554.61) 1(6134.96,554.61) 1(6134.96,588.45) 1(6134.96,588.45) 1(6138.46,556.95) 1(6138.46,556.95) 1(6138.46,586.11) 1(6138.46,586.11) 1(6141.46,560.45) 1(6141.46,560.45) 1(6141.46,582.61) 1(6141.46,582.61) 1(6143.46,564.53) 1(6143.46,564.53) 1(6143.46,578.53) 1(6143.46,578.53) 1(6144.46,569.2) 1(6144.46,569.2) 1(6144.46,573.86) 1(6144.46,573.86) 1(6148.26,1422.69) 1(6148.26,1422.69) 1(6148.26,1457.69) 1(6149.46,554.03) 1(6149.46,589.03) 1(6149.46,589.03) 1(6172.46,554.03) 1(6172.46,554.03) 1(6172.46,589.03) 1(6212.55,2203.21) 1(6212.55,2422.89) 1(6212.55,2642.58) 1(6212.55,2862.26) 1(6212.55,3081.95) 1(6212.55,3301.63) 1(6212.55,3521.32) 1(6262.55,2203.21) 1(6262.55,2422.89) 1(6262.55,2642.58) 1(6262.55,2862.26) 1(6262.55,3081.95) 1(6262.55,3301.63) 1(6262.55,3521.32) 1(6312.55,2203.21) 1(6312.55,2422.89) 1(6312.55,2642.58) 1(6312.55,2862.26) 1(6312.55,3081.95) 1(6312.55,3301.63) 1(6312.55,3521.32) 1(6322.55,2093.21) 1(6322.55,2312.89) 1(6322.55,2532.58) 1(6322.55,2752.26) 1(6322.55,2971.95) 1(6322.55,3191.63) 1(6322.55,3411.32) 1(6362.55,2203.21) 1(6362.55,2422.89) 1(6362.55,2642.58) 1(6362.55,2862.26) 1(6362.55,3081.95) 1(6362.55,3301.63) 1(6362.55,3521.32) 1(6372.55,2093.21) 1(6372.55,2312.89) 1(6372.55,2532.58) 1(6372.55,2752.26) 1(6372.55,2971.95) 1(6372.55,3191.63) 1(6372.55,3411.32) 1(6412.55,2203.21) 1(6412.55,2422.89) 1(6412.55,2642.58) 1(6412.55,2862.26) 1(6412.55,3081.95) 1(6412.55,3301.63) 1(6412.55,3521.32) 1(6422.55,2093.21) 1(6422.55,2312.89) 1(6422.55,2532.58) 1(6422.55,2752.26) 1(6422.55,2971.95) 1(6422.55,3191.63) 1(6422.55,3411.32) 1(6472.55,2093.21) 1(6472.55,2143.21) 1(6472.55,2312.89) 1(6472.55,2362.89) 1(6472.55,2532.58) 1(6472.55,2582.58) 1(6472.55,2752.26) 1(6472.55,2802.26) 1(6472.55,2971.95) 1(6472.55,3021.95) 1(6472.55,3191.63) 1(6472.55,3241.63) 1(6472.55,3411.32) 1(6472.55,3461.32) 1(6490.44,2036.59) 1(6490.44,2036.59) 1(6490.44,2036.59) 1(6490.44,2256.59) 1(6490.44,2256.59) 1(6490.44,2256.59) 1(6490.44,2476.59) 1(6490.44,2476.59) 1(6490.44,2476.59) 1(6490.44,2696.59) 1(6490.44,2696.59) 1(6490.44,2696.59) 1(6490.44,2916.59) 1(6490.44,2916.59) 1(6490.44,2916.59) 1(6490.44,3136.59) 1(6490.44,3136.59) 1(6490.44,3136.59) 1(6490.44,3356.59) 1(6490.44,3356.59) 1(6490.44,3356.59) 1(6490.44,3576.59) 1(6490.44,3576.59) 1(6490.44,3576.59) 1(6545.44,2016.59) 1(6545.44,2016.59) 1(6545.44,2056.59) 1(6545.44,2056.59) 1(6545.44,2236.59) 1(6545.44,2236.59) 1(6545.44,2276.59) 1(6545.44,2276.59) 1(6545.44,2456.59) 1(6545.44,2456.59) 1(6545.44,2496.59) 1(6545.44,2496.59) 1(6545.44,2676.59) 1(6545.44,2676.59) 1(6545.44,2716.59) 1(6545.44,2716.59) 1(6545.44,2896.59) 1(6545.44,2896.59) 1(6545.44,2936.59) 1(6545.44,2936.59) 1(6545.44,3116.59) 1(6545.44,3116.59) 1(6545.44,3156.59) 1(6545.44,3156.59) 1(6545.44,3336.59) 1(6545.44,3336.59) 1(6545.44,3376.59) 1(6545.44,3376.59) 1(6545.44,3556.59) 1(6545.44,3556.59) 1(6545.44,3596.59) 1(6545.44,3596.59) 1(6626.44,2036.59) 1(6626.44,2256.59) 1(6626.44,2476.59) 1(6626.44,2696.59) 1(6626.44,2916.59) 1(6626.44,3136.59) 1(6626.44,3356.59) 1(6626.44,3576.59) 1(6699.02,2011.32) 1(6699.02,2011.32) 1(6699.02,2053.32) 1(6699.02,2053.32) 1(6699.02,2231.32) 1(6699.02,2231.32) 1(6699.02,2273.32) 1(6699.02,2273.32) 1(6699.02,2451.32) 1(6699.02,2451.32) 1(6699.02,2493.32) 1(6699.02,2493.32) 1(6699.02,2671.32) 1(6699.02,2671.32) 1(6699.02,2713.32) 1(6699.02,2713.32) 1(6699.02,2891.32) 1(6699.02,2891.32) 1(6699.02,2933.32) 1(6699.02,2933.32) 1(6699.02,3111.32) 1(6699.02,3111.32) 1(6699.02,3153.32) 1(6699.02,3153.32) 1(6699.02,3331.32) 1(6699.02,3331.32) 1(6699.02,3373.32) 1(6699.02,3373.32) 1(6699.02,3551.32) 1(6699.02,3551.32) 1(6699.02,3593.32) 1(6699.02,3593.32) 1(6702.94,2000.82) 1(6702.94,2000.82) 1(6702.94,2063.82) 1(6702.94,2063.82) 1(6702.94,2220.82) 1(6702.94,2220.82) 1(6702.94,2283.82) 1(6702.94,2283.82) 1(6702.94,2440.82) 1(6702.94,2440.82) 1(6702.94,2503.82) 1(6702.94,2503.82) 1(6702.94,2660.82) 1(6702.94,2660.82) 1(6702.94,2723.82) 1(6702.94,2723.82) 1(6702.94,2880.82) 1(6702.94,2880.82) 1(6702.94,2943.82) 1(6702.94,2943.82) 1(6702.94,3100.82) 1(6702.94,3100.82) 1(6702.94,3163.82) 1(6702.94,3163.82) 1(6702.94,3320.82) 1(6702.94,3320.82) 1(6702.94,3383.82) 1(6702.94,3383.82) 1(6702.94,3540.82) 1(6702.94,3540.82) 1(6702.94,3603.82) 1(6702.94,3603.82) 1(6710.77,1990.32) 1(6710.77,2074.32) 1(6710.77,2210.32) 1(6710.77,2294.32) 1(6710.77,2430.32) 1(6710.77,2514.32) 1(6710.77,2650.32) 1(6710.77,2734.32) 1(6710.77,2870.32) 1(6710.77,2954.32) 1(6710.77,3090.32) 1(6710.77,3174.32) 1(6710.77,3310.32) 1(6710.77,3394.32) 1(6710.77,3530.32) 1(6710.77,3614.32) 1(7169.22,1427.7) 1(7169.22,1444.62) 1(7169.22,1462.7) 1(7169.22,1462.7) 1(7181.04,565.85) 1(7181.04,582.77) 1(7181.04,600.85) 1(7181.04,600.85) 1(7181.72,1444.62) 1(7181.72,1444.62) 1(7181.72,1444.62) 1(7181.72,1462.7) 1(7181.72,1462.7) 1(7185.22,1446.37) 1(7185.22,1446.37) 1(7185.72,1460.95) 1(7185.72,1460.95) 1(7188.22,1449.28) 1(7188.22,1449.28) 1(7188.22,1458.62) 1(7188.22,1458.62) 1(7189.22,1427.7) 1(7189.22,1453.95) 1(7189.22,1453.95) 1(7193.54,582.77) 1(7193.54,582.77) 1(7193.54,582.77) 1(7193.54,600.85) 1(7193.54,600.85) 1(7197.04,584.52) 1(7197.04,584.52) 1(7197.54,599.1) 1(7197.54,599.1) 1(7199.22,1427.7) 1(7199.22,1427.7) 1(7199.22,1445.78) 1(7199.22,1462.7) 1(7199.22,1462.7) 1(7200.04,587.43) 1(7200.04,587.43) 1(7200.04,596.77) 1(7200.04,596.77) 1(7201.04,565.85) 1(7201.04,592.1) 1(7201.04,592.1) 1(7211.04,565.85) 1(7211.04,565.85) 1(7211.04,583.93) 1(7211.04,600.85) 1(7211.04,600.85) 1(7211.22,1445.78) 1(7219.22,1427.7) 1(7219.22,1462.7) 1(7222.61,1990.32) 1(7222.61,2074.32) 1(7222.61,2210.32) 1(7222.61,2294.32) 1(7222.61,2430.32) 1(7222.61,2514.32) 1(7222.61,2650.32) 1(7222.61,2734.32) 1(7222.61,2870.32) 1(7222.61,2954.32) 1(7222.61,3090.32) 1(7222.61,3174.32) 1(7222.61,3310.32) 1(7222.61,3394.32) 1(7223.04,583.93) 1(7226.22,1427.7) 1(7226.22,1462.7) 1(7226.22,1462.7) 1(7230.44,2000.82) 1(7230.44,2000.82) 1(7230.44,2063.82) 1(7230.44,2063.82) 1(7230.44,2220.82) 1(7230.44,2220.82) 1(7230.44,2283.82) 1(7230.44,2283.82) 1(7230.44,2440.82) 1(7230.44,2440.82) 1(7230.44,2503.82) 1(7230.44,2503.82) 1(7230.44,2660.82) 1(7230.44,2660.82) 1(7230.44,2723.82) 1(7230.44,2723.82) 1(7230.44,2880.82) 1(7230.44,2880.82) 1(7230.44,2943.82) 1(7230.44,2943.82) 1(7230.44,3100.82) 1(7230.44,3100.82) 1(7230.44,3163.82) 1(7230.44,3163.82) 1(7230.44,3320.82) 1(7230.44,3320.82) 1(7230.44,3383.82) 1(7230.44,3383.82) 1(7231.04,565.85) 1(7231.04,600.85) 1(7233.39,3530.41) 1(7233.39,3614.41) 1(7234.36,2011.32) 1(7234.36,2011.32) 1(7234.36,2053.32) 1(7234.36,2053.32) 1(7234.36,2231.32) 1(7234.36,2231.32) 1(7234.36,2273.32) 1(7234.36,2273.32) 1(7234.36,2451.32) 1(7234.36,2451.32) 1(7234.36,2493.32) 1(7234.36,2493.32) 1(7234.36,2671.32) 1(7234.36,2671.32) 1(7234.36,2713.32) 1(7234.36,2713.32) 1(7234.36,2891.32) 1(7234.36,2891.32) 1(7234.36,2933.32) 1(7234.36,2933.32) 1(7234.36,3111.32) 1(7234.36,3111.32) 1(7234.36,3153.32) 1(7234.36,3153.32) 1(7234.36,3331.32) 1(7234.36,3331.32) 1(7234.36,3373.32) 1(7234.36,3373.32) 1(7238.04,565.85) 1(7238.04,600.85) 1(7238.04,600.85) 1(7239.22,1433.53) 1(7239.22,1433.53) 1(7241.22,3540.91) 1(7241.22,3540.91) 1(7241.22,3603.91) 1(7241.22,3603.91) 1(7245.14,3551.41) 1(7245.14,3551.41) 1(7245.14,3593.41) 1(7245.14,3593.41) 1(7251.04,571.68) 1(7251.04,571.68) 1(7252.22,1427.7) 1(7252.22,1462.7) 1(7252.22,1462.7) 1(7256.72,1427.7) 1(7261.22,1439.95) 1(7264.04,565.85) 1(7264.04,600.85) 1(7264.04,600.85) 1(7268.54,565.85) 1(7269.22,1462.7) 1(7269.22,1462.7) 1(7273.04,578.1) 1(7277.22,1439.95) 1(7281.04,600.85) 1(7281.04,600.85) 1(7281.72,1427.7) 1(7289.04,578.1) 1(7289.22,1427.7) 1(7289.22,1444.62) 1(7289.22,1462.7) 1(7289.22,1462.7) 1(7293.54,565.85) 1(7301.04,565.85) 1(7301.04,582.77) 1(7301.04,600.85) 1(7301.04,600.85) 1(7301.72,1444.62) 1(7301.72,1444.62) 1(7301.72,1444.62) 1(7301.72,1462.7) 1(7301.72,1462.7) 1(7305.22,1446.37) 1(7305.22,1446.37) 1(7305.72,1460.95) 1(7305.72,1460.95) 1(7308.22,1449.28) 1(7308.22,1449.28) 1(7308.22,1458.62) 1(7308.22,1458.62) 1(7309.22,1427.7) 1(7309.22,1453.95) 1(7309.22,1453.95) 1(7313.54,582.77) 1(7313.54,582.77) 1(7313.54,582.77) 1(7313.54,600.85) 1(7313.54,600.85) 1(7317.04,584.52) 1(7317.04,584.52) 1(7317.54,599.1) 1(7317.54,599.1) 1(7318.22,1427.7) 1(7318.22,1441.12) 1(7318.22,1462.7) 1(7320.04,587.43) 1(7320.04,587.43) 1(7320.04,596.77) 1(7320.04,596.77) 1(7321.04,565.85) 1(7321.04,592.1) 1(7321.04,592.1) 1(7326.72,1451.03) 1(7330.04,565.85) 1(7330.04,579.27) 1(7330.04,600.85) 1(7337.22,1462.7) 1(7338.54,589.18) 1(7340.22,1427.7) 1(7349.04,600.85) 1(7352.04,565.85)
  round 10 on Drill Drawing: 1(4386.54,1983.95) 1(4386.54,1983.95) 1(4386.54,1983.95) 1(4386.54,2093.79) 1(4386.54,2203.63) 1(4386.54,2313.48) 1(4386.54,2423.32) 1(4386.54,2533.16) 1(4386.54,2643) 1(4386.54,2752.85) 1(4386.54,2862.69) 1(4386.54,2972.53) 1(4386.54,3082.37) 1(4386.54,3192.22) 1(4386.54,3302.06) 1(4386.54,3411.9) 1(4386.54,3521.75) 1(4386.54,3631.59) 1(4386.54,3631.59) 1(6473.55,1983.95) 1(6473.55,1983.95) 1(6473.55,1983.95) 1(6473.55,2093.79) 1(6473.55,2203.63) 1(6473.55,2313.48) 1(6473.55,2423.32) 1(6473.55,2533.16) 1(6473.55,2643) 1(6473.55,2752.85) 1(6473.55,2862.69) 1(6473.55,2972.53) 1(6473.55,3082.37) 1(6473.55,3192.22) 1(6473.55,3302.06) 1(6473.55,3411.9) 1(6473.55,3521.75) 1(6473.55,3631.59) 1(6473.55,3631.59)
